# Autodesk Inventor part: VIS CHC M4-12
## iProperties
Created: 2004-11
Part Number: VIS CHC M4-12
Document SubType Name: Modeling
Designer: Bruno
Manufacturer: Standard
Standards Organization: Custom
Author: Bruno
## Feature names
1. Base1
